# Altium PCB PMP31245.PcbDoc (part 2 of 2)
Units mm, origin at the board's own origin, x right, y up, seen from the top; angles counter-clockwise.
Board outline 106.43 x 50.29 mm, 4 copper layers (Top Layer, GND, Layer 2, Bottom Layer), stack 0.603 mm thick; 132 components, 64 nets, 341 pads, 146 vias.
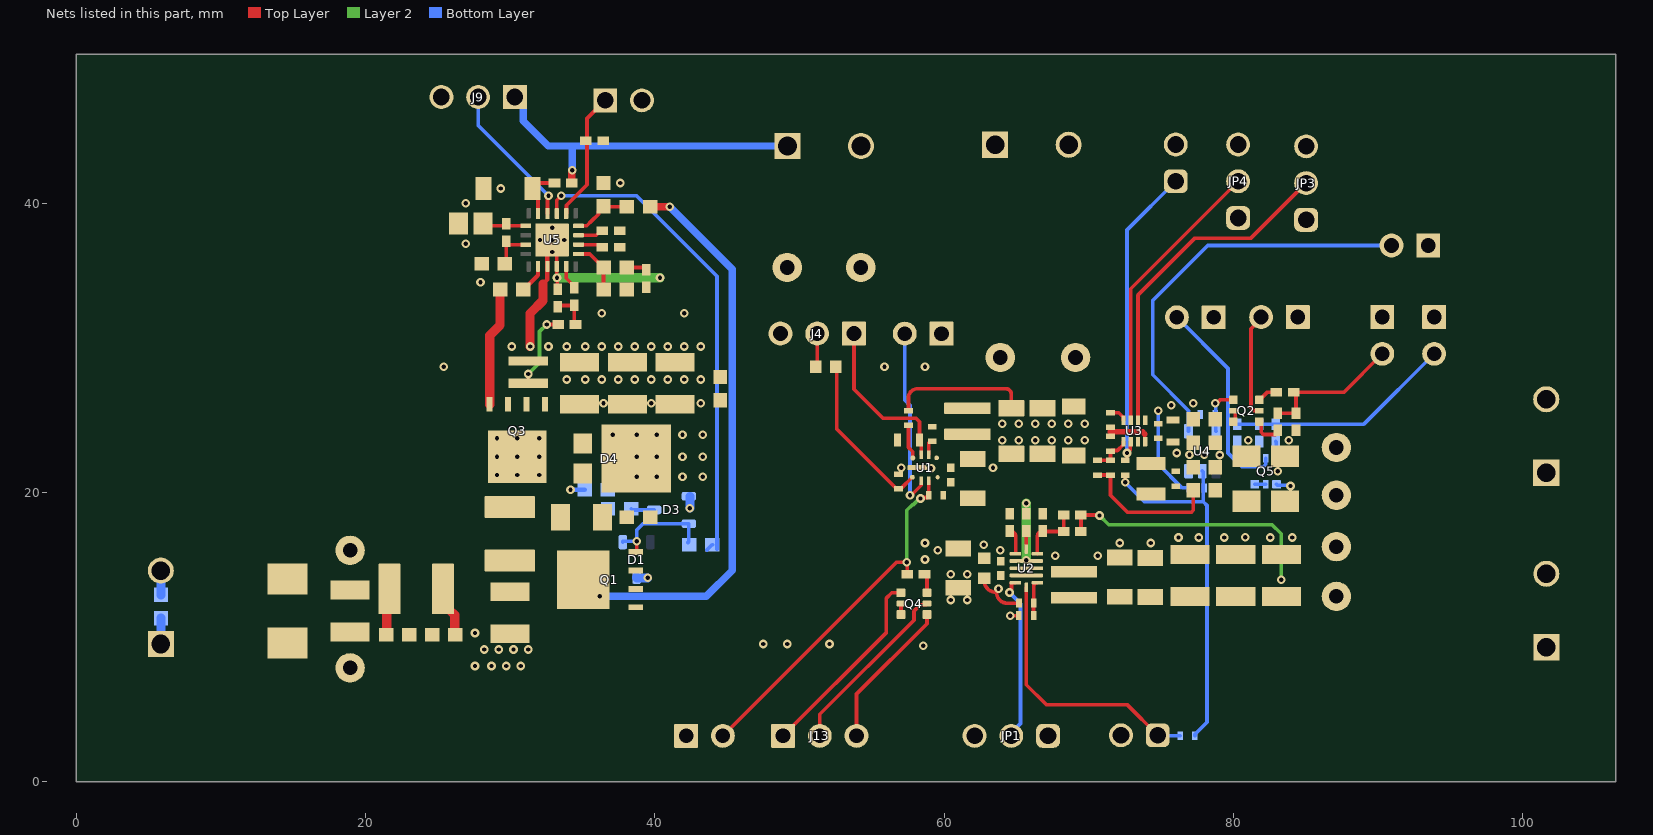
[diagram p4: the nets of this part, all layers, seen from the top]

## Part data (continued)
U4: library part CMP-0051406-2, "Single Buffer/Driver With Open-Drain Output, DBV0005A (SOT-23-5)", F @ Nom Voltage(Max)(Mhz)=250, Generic Part Number=SN74AUC1G07, ICC @ Nom Voltage(Max)(mA)=0.01, Manufacturer="Texas Instruments", Operating Temperature Range="-40 to 85 C", Rating=Catalog, tpd @ Nom Voltage(Max)(ns)=4.7,3.3,2.4,2.3,1.8, Voltage(Nom)(V)=0.8,1.2,1.5,1.8,2.5
U5: library part LM5150RUMQ1, "Wide VIN Automotive Low IQ Boost Controller, RUM0016C (WQFN-16)", Alternate Manufacturer="Texas Instruments"

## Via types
v1: diameter 0.6, hole 0.3, Top Layer to Bottom Layer, tented both sides, 143 vias
v2: diameter 0.6/0.6/0.6/0.6 (per signal layer), hole 0.3, Top Layer to Bottom Layer, tented both sides, 2 vias
v3: diameter 0.58, hole 0.3, Top Layer to Bottom Layer, tented both sides, 1 vias

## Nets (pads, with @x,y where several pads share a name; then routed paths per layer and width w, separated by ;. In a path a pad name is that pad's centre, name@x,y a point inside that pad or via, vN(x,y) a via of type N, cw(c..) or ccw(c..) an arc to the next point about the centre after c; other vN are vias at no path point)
3V3: C20.1 C21.1 C22.1 C23.1 C24.1 C25.1 J6.1 L3.2 Q5.4 R10.2 TP6.1 | length 10.9
  Top Layer w0.254: R10.2@70.612,21.209 C20.1@71.501,21.209 71.501,19.812 72.688,18.625 77.067,18.625 77.216,18.774 C23.1@77.216,20.155
  Bottom Layer w0.254: Q5.4@82.986,20.564 83.044,20.505 83.889,20.505 v1(83.947,20.447)
5V: C4.2 C5.2 C6.2 C9.1 C11.1 C12.1 C26.1 C27.1 C28.1 C29.2 C33.1 J1.1 JP1.1 JP3.1 JP4.1 L1.2 Q2.4 R2.1 R5.1 R33.2 TP1.1 U2.2@65.684,14.265 U3.1 U4.5 | length 23
  Top Layer w0.254: R2.1@57.531,25.654 57.531,26.543 cw(c58.166,26.543) 58.166,27.178 64.262,27.178 cw(c64.262,26.797) 64.643,26.797 C4.2@64.643,25.832 ; C11.1@62.763,14.065 62.763,13.945 ccw(c63.627,13.945) 63.627,13.081 ccw(c64.356,13.081) 64.356,12.352 R5.1@65.176,12.352 ; v1(78.74,26.162) 78.834,26.162 79.076,26.404 Q2.4@79.999,26.404 Q2.4@80.126,26.404
  Bottom Layer w0.254: v1(74.803,25.654) 74.803,21.971 76.454,20.32 R33.2@76.962,20.32 ; v1(78.74,26.162) 78.771,26.131 78.771,24.265 U4.5@78.801,24.235
  other v1: 60.452,12.573 61.595,12.573 63.754,13.335 60.452,14.351 61.595,14.351 64.008,24.765 65.151,24.765 66.294,24.765 67.437,24.765 68.58,24.765 69.723,24.765 75.692,26.035 77.216,26.162
12V: C1.2 C2.1 C31.1 C38.1 C39.1 C40.1 C41.1 D1.3 D4.3 J8.1 J9.1 Q1.1 Q1.2 Q1.3 R1.2 R21.2 TP10.1 U1.4 | length 24.3
  Top Layer w0.508: R21.2@34.255,41.402 34.255,42.256 v1(34.29,42.291)
  Bottom Layer w0.508: J9.1@30.319,47.347 30.89,46.776 30.89,45.691 32.62,43.961 34.29,43.961 ; v1(34.29,42.291) 34.29,43.961 ; J8.1@49.165,43.961 34.29,43.961
  Bottom Layer w0.635: D1.3@38.735,14.167 ccw(c38.805,14.167) 38.805,14.097 v1(39.497,14.097)
  other v1: 38.735,21.082 40.132,21.082 41.91,21.082 43.307,21.082 37.084,22.479 38.735,22.479 40.132,22.479 41.91,22.479 43.307,22.479 37.084,24.003 38.735,24.003 40.132,24.003 41.91,24.003 43.307,24.003 36.449,26.162 39.751,26.162 43.18,26.162
EN_LMR: J2.2 R1.1 R30.2 U1.3 | length 25.1
  Top Layer w0.254: J2.2@44.7,3.175 56.71,15.185 v1(57.419,15.185) ; R30.2@57.439,14.351 v1@57.439,15.185 ; v1(58.362,19.589) 58.428,19.655 58.864,19.655 58.926,19.716 58.926,20.815 U1.3@58.924,20.817
  Layer 2 w0.254: v1(57.419,15.185) 57.419,18.768 57.796,19.145 57.843,19.145 58.286,19.589 v1(58.362,19.589)
GND: C1.1 C2.2 C4.1 C5.1 C6.1 C7.2 C8.2 C9.2 C10.2 C11.2 C12.2 C14.2 C15.2 C16.2 C17.2 C18.2 C19.2 C21.2 C22.2 C23.2 C24.2 C25.2 C26.2 C27.2 C28.2 C29.1 C30.1 C33.2 C34.2 C35.1 C36.1 C37.2 C38.2 C39.2 C40.2 C41.2 C42.1 C43.1 C44.2 C45.2 C46.1 C48.2 D2.1 D3.1 J1.2 J2.1 J3.1 J4.3 J5.2 J6.2 J7.1 J8.2 J9.3 J10.2 J11.1 J12.1 J14.1 J15.1 J16.1 JP1.3 JP2.2 JP3.3 JP4.3 JP5.2 Q2.1 Q5.1 R3.2 R7.2 R8.1 R9.1 R11.1 R12.1 R19.1 R22.1 R23.1 R24.1 R26.1 R28.1 R32.1 TP2.1 TP5.1 TP7.1 TP9.1 TP11.1 U1.9 U2.4@65.684,15.265 U3.8 U4.3 U5.10 U5.11 U5.17@32.893,37.465 | length 31.6
  Top Layer w0.254: v1(32.893,37.465) 33.218,37.14 U5.11@33.218,35.64 33.221,35.637 33.221,34.851 v1(33.225,34.847) 33.251,34.821 33.251,34.151 C43.1@33.274,34.128 ; v1(64.57,11.487) R7.2@65.165,11.487 ; R11.1@71.501,23.876 71.501,24.194 R12.1@71.501,24.511 ; 73.879,24.038 73.879,23.54 U3.8@73.902,23.517 ; Q2.1@81.926,24.904 81.926,24.163 82.075,24.014 82.907,24.014 82.912,24.019 83.012,24.019 83.185,24.192 R28.1@83.185,24.292
  Top Layer w0.305: 32.258,34.417 32.568,34.727 U5.10@32.568,35.64 32.568,37.14 v1(32.893,37.465)
  Top Layer w0.381: 71.501,24.194 73.724,24.194 73.879,24.038
  Top Layer w0.635: v1(31.369,30.099) 31.369,32.385 32.258,33.274 32.258,34.417
  Layer 2 w0.635: v1(33.225,34.847) v2(40.354,34.846) v2(40.354,34.846) ; v3(65.679,15.316) v2(65.679,19.253)
  Bottom Layer w0.635: J7.1@5.834,9.517 5.843,9.526 5.843,11.312 C30.1@5.851,11.32 ; v1(42.418,18.923) D3.1@42.418,19.729
  other v1: 27.559,8.001 28.702,8.001 29.718,8.001 30.734,8.001 28.194,9.144 29.21,9.144 30.226,9.144 31.242,9.144 58.547,9.398 47.498,9.525 49.149,9.525 52.07,9.525 27.559,10.287 58.674,15.367 67.691,15.621 70.612,15.621 59.563,16.002 63.881,16.002 62.738,16.383 58.674,16.51 72.136,16.51 74.295,16.51 76.2,16.891 77.597,16.891 79.375,16.891 82.55,16.891 84.074,16.891 80.814,16.904 83.058,21.463 59.089,21.679 57.023,21.717 63.373,21.717 79.067,22.592 76.962,22.606 77.978,22.606 76.073,22.733 64.008,23.622 65.151,23.622 66.294,23.622 67.437,23.622 68.58,23.622 69.723,23.622 81.026,23.622 83.82,23.622 33.909,27.813 35.179,27.813 36.322,27.813 37.465,27.813 38.608,27.813 39.751,27.813 40.894,27.813 42.037,27.813 43.18,27.813 25.4,28.702 55.88,28.702 58.674,28.702 30.099,30.099 32.639,30.099 33.909,30.099 35.179,30.099 36.322,30.099 37.465,30.099 38.608,30.099 39.751,30.099 40.894,30.099 42.037,30.099 43.18,30.099 36.322,32.385 42.037,32.385 27.94,34.544 32.893,36.627 26.924,37.211 32.055,37.465 33.731,37.465 32.893,38.303 26.924,40.005 29.337,41.021 37.592,41.402
MODE: JP4.2 U3.3 | length 19.6
  Top Layer w0.254: U3.3@72.902,24.997 72.902,34.096 JP4.2@80.328,41.522
MODE/SYNC: R3.1 R4.2 U1.1 | length 11.7
  Top Layer w0.254: R4.2@52.578,28.829 52.578,24.392 56.723,20.247 R3.1@56.838,20.247 56.901,20.31 57.052,20.31 U1.1@57.797,21.056
NetC3_1: C3.1 U1.6 | length 1.1
  Top Layer w0.254: U1.6@58.924,22.617 58.924,23.403 59.064,23.543 C3.1@59.178,23.543
NetC3_2: C3.2 L1.1 U1.5
NetC7_1: C7.1 J12.2 R27.2 R28.2 | length 10
  Top Layer w0.254: R28.2@83.058,25.492 C7.1@84.328,25.492 84.328,26.762 R27.2@84.166,26.924 87.63,26.924 J12.2@90.297,29.591
NetC8_1: C8.1 J4.1 U1.7 | length 11.6
  Top Layer w0.254: J4.1@53.761,30.992 53.761,27.138 55.753,25.146 58.039,25.146 58.293,24.892 C8.1@58.293,23.622 58.293,23.431 58.424,23.3 U1.7@58.424,22.617
NetC10_1: C10.1 J15.2 R31.2 R32.2 | length 15.6
  Bottom Layer w0.254: R32.2@80.264,24.73 R31.2@82.931,24.73 89.023,24.73 J15.2@93.884,29.591
NetC13_2: C13.2 R6.1 R8.2 U2.5 | length 4.4
  Top Layer w0.254: U2.5@66.444,15.765 66.444,16.958 cw(c66.827,16.958) R8.2@66.827,17.34 ccw(c66.862,17.34) 66.862,17.305 R6.1@68.259,17.305 C13.2@68.259,18.448
NetC19_1: C19.1 U2.6 | length 1.3
  Top Layer w0.254: U2.6@65.684,16.09 C19.1@65.684,17.34
NetC20_2: C20.2 R10.1 R11.2 U3.5 | length 2.8
  Top Layer w0.254: R10.1@70.612,22.225 C20.2@71.501,22.225 R11.2@71.501,22.86 71.55,22.909 71.978,22.909 72.378,23.309 72.402,23.332 U3.5@72.402,23.517
NetC30_2: C30.2 C34.1 C35.2 D2.2 J7.2 L4.1 TP8.1 | length 4.9
  Top Layer w0.635: C35.2@21.454,10.164 21.454,13.144 L4.1@21.645,13.335
  Bottom Layer w0.635: J7.2@5.834,14.597 5.843,14.588 5.843,12.929 C30.2@5.851,12.92
NetC31_2: C31.2 R14.2
NetC32_1: C32.1 R13.1 | length 0.1
  Bottom Layer w0.305: C32.1@36.741,20.193 C32.1@36.792,20.244
NetC32_2: C32.2 D4.1 D4.2 L5.2 Q3.5 R14.1 | length 1
  Bottom Layer w0.305: v1(34.163,20.193) C32.2@35.141,20.193
  other v1: 29.083,21.209 30.48,21.209 32.004,21.209 29.083,22.479 30.48,22.479 32.004,22.479 29.083,23.749 30.48,23.749 32.004,23.749
NetC36_2: C36.2 C37.1 L4.2 L5.1 Q1.5 R15.1 | length 41.6
  Top Layer w0.508: R15.1@39.662,39.751 v1(41.021,39.751)
  Top Layer w0.635: L4.2@25.345,13.335 25.345,12.335 25.778,11.902 25.786,11.902 26.158,11.531 C36.2@26.158,10.202
  Bottom Layer w0.508: v1(36.195,12.827) 43.561,12.827 45.339,14.605 45.339,35.433 v1(41.021,39.751)
NetC42_2: C42.2 R15.2 U5.16 | length 4
  Top Layer w0.254: U5.16@34.718,38.44 35.292,38.44 35.657,38.805 36.101,39.249 36.101,39.454 C42.2@36.449,39.802 36.5,39.751 R15.2@38.062,39.751
NetC43_2: C43.2 R18.1 R20.2 | length 2.5
  Top Layer w0.254: C43.2@33.274,32.928 34.39,32.928 R20.2@34.419,32.957 34.419,31.713 R18.1@34.509,31.623
NetC44_1: C44.1 R21.1 U5.4 | length 3.6
  Top Layer w0.254: U5.4@31.918,39.29 31.918,40.648 C44.1@31.545,41.021 31.926,41.402 R21.1@33.055,41.402
NetC45_1: C45.1 R25.1 U5.7 | length 3
  Top Layer w0.254: C45.1@29.629,35.814 29.718,35.903 R25.1@29.718,37.313 ; R25.1@29.718,37.373 R25.1@29.718,37.313 ; U5.7@31.068,37.14 29.891,37.14 R25.1@29.718,37.313
NetC47_1: C47.1 C48.1 U5.13 | length 3.6
  Top Layer w0.254: U5.13@34.718,36.49 35.494,36.49 36.424,35.56 C47.1@36.449,35.56 C48.1@36.449,34.036
NetC47_2: C47.2 R26.2 | length 1.4
  Top Layer w0.254: C47.2@38.049,35.56 39.246,35.56 R26.2@39.408,35.398
NetD1_1: D1.1 D3.2 Q1.4 R16.1 | length 7.7
  Top Layer w0.254: Q1.4@38.662,15.875 ccw(c38.662,15.948) 38.735,15.948 v1(38.735,16.637)
  Bottom Layer w0.254: D1.1@37.785,16.567 cw(c37.855,16.567) 37.855,16.637 v1(38.735,16.637) 38.735,17.399 39.182,17.846 D3.2@42.348,17.846 42.348,16.605 R16.1@42.291,16.548
NetD3_3: D3.3 R13.2 | length 1.6
  Bottom Layer w0.254: R13.2@38.357,18.869 38.43,18.796 D3.3@39.948,18.796
NetJ4_2: J4.2 R4.1 | length 2.2
  Top Layer w0.254: R4.1@51.178,28.829 51.221,28.872 J4.2@51.221,30.992
NetJ9_2: J9.2 U5.3 | length 10.1
  Top Layer w0.254: U5.3@32.568,39.29 32.568,40.442 v1(32.639,40.513)
  Bottom Layer w0.254: J9.2@27.779,47.347 27.779,45.373 v1(32.639,40.513)
NetJ10_1: J10.1 R22.2 U5.1 | length 8.9
  Top Layer w0.254: U5.1@33.868,39.29 33.891,39.313 33.891,39.86 35.306,41.275 35.306,45.859 J10.1@36.564,47.118
NetJ11_2: J11.2 Q2.2 | length 7.2
  Top Layer w0.254: Q2.2@81.799,25.654 81.429,25.654 81.22,25.863 81.22,31.331 81.915,32.027 J11.2@81.915,32.131
NetJ13_1: J13.1 Q4.1 | length 13.6
  Top Layer w0.254: J13.1@48.862,3.175 56.007,10.32 56.007,12.7 56.376,13.069 Q4.1@57.012,13.069
NetJ13_2: J13.2 Q4.5 | length 12.4
  Top Layer w0.254: J13.2@51.402,3.175 51.402,4.666 57.912,11.176 57.912,11.811 58.347,12.246 58.739,12.246 Q4.5@58.812,12.319
NetJ13_3: J13.3 Q4.4 | length 10.4
  Top Layer w0.254: J13.3@53.942,3.175 53.942,6.063 58.812,10.933 Q4.4@58.812,11.569
NetJ14_2: J14.2 Q5.2 | length 14.3
  Bottom Layer w0.254: J14.2@76.093,32.118 79.629,28.582 79.629,22.733 80.578,21.784 82.087,21.784 82.236,21.933 Q5.2@82.236,22.364
NetJ16_2: J16.2 U4.4 | length 28.2
  Bottom Layer w0.254: U4.4@76.901,24.235 76.901,25.658 74.422,28.137 74.422,33.274 78.232,37.084 J16.2@90.932,37.084
NetJP1_2: JP1.2 U2.8 | length 11.5
  Top Layer w0.254: v1(64.516,13.081) 64.516,13.175 64.662,13.321 64.662,13.763 64.664,13.765 U2.8@64.923,13.765
  Bottom Layer w0.254: v1(64.516,13.081) 65.278,12.319 65.278,4.022 64.643,3.387 JP1.2@64.643,3.175
NetJP3_2: JP3.2 U3.2 | length 23.5
  Top Layer w0.254: U3.2@73.402,24.997 73.402,33.651 77.343,37.592 81.224,37.592 JP3.2@85.027,41.395
NetL2_1: L2.1 U2.3@65.684,14.765
NetL3_1: L3.1 U3.7
NetQ2_3: Q2.3 R27.1 | length 1.4
  Top Layer w0.254: Q2.3@81.799,26.404 82.319,26.924 R27.1@82.966,26.924
NetQ2_5: Q2.5 Q2.6 | length 0.8
  Top Layer w0.254: Q2.6@80.126,24.904 Q2.5@80.126,25.654
NetQ3_1: Q3.1 Q3.2 Q3.3 R18.2 R19.2 | length 5.4
  Top Layer w0.254: R19.2@31.242,27.546 v1(31.242,28.194) ; v1(32.512,31.623) R18.2@33.309,31.623
  Layer 2 w0.254: v1(31.242,28.194) 32.022,28.974 32.022,31.133 v1(32.512,31.623)
NetQ3_4: Q3.4 R17.2 | length 8.2
  Top Layer w0.635: Q3.4@28.575,26.089 28.575,30.861 29.299,31.585 R17.2@29.299,34.036
NetQ4_2: Q4.2 Q4.3 | length 0.8
  Top Layer w0.254: Q4.3@57.012,11.569 Q4.2@57.012,12.319
NetQ4_6: Q4.6 R30.1 | length 1.4
  Top Layer w0.254: R30.1@58.639,14.351 58.812,14.178 Q4.6@58.812,13.069
NetQ5_3: Q5.3 R31.1 | length 1.2
  Bottom Layer w0.254: R31.1@82.931,23.53 82.959,23.502 82.959,22.391 Q5.3@82.986,22.364
NetQ5_5: Q5.5 Q5.6 | length 0.8
  Bottom Layer w0.254: Q5.6@81.486,20.564 Q5.5@82.236,20.564
NetR2_2: R2.2 U1.8 | length 2.4
  Top Layer w0.254: R2.2@57.531,24.638 57.531,23.121 57.833,22.819 U1.8@57.833,22.382
NetR5_2: R5.2 R7.1 U2.1 | length 2.4
  Top Layer w0.254: R7.1@66.181,11.487 66.181,12.352 R5.2@66.192,12.352 66.192,13.512 cw(c66.444,13.512) U2.1@66.444,13.765
NetR9_2: R9.2 U2.7 | length 1.6
  Top Layer w0.254: R9.2@64.541,17.34 cw(c64.541,16.923) 64.958,16.923 64.958,15.93
NetR12_2: R12.2 U3.4 | length 1.2
  Top Layer w0.254: R12.2@71.501,25.527 71.508,25.52 72.064,25.52 72.379,25.205 72.402,25.182 U3.4@72.402,24.997
NetR16_2: R16.2 U5.2 | length 33.8
  Top Layer w0.254: U5.2@33.218,39.29 33.218,40.203 v1(33.528,40.513)
  Bottom Layer w0.254: v1(33.528,40.513) 38.735,40.513 44.291,34.957 R16.2@44.291,16.097 ; R16.2@43.607,16.01 43.607,16.035 43.955,16.383 R16.2@43.98,16.383
NetR17_1: R17.1 U5.9 | length 2
  Top Layer w0.305: R17.1@30.899,34.036 30.924,34.036 31.916,35.028 31.916,35.638 U5.9@31.918,35.64
NetR20_1: R20.1 U5.12 | length 1.7
  Top Layer w0.254: U5.12@33.868,35.64 33.868,34.808 34.419,34.257 R20.1@34.419,34.157
NetR23_2: R23.2 U5.14 | length 1.7
  Top Layer w0.254: U5.14@34.718,37.14 36.174,37.14 cw(c36.174,36.957) R23.2@36.357,36.957
NetR24_2: R24.2 U5.15 | length 1.8
  Top Layer w0.254: U5.15@34.718,37.79 35.947,37.79 36.257,38.1 R24.2@36.357,38.1
PG_3V3: JP5.1 R34.1 U3.6 | length 21.7
  Top Layer w0.254: R34.1@72.517,22.225 72.581,22.225 72.644,22.288 v1(72.644,22.733) 72.879,22.968 72.879,23.494 U3.6@72.902,23.517
  Bottom Layer w0.254: v1(72.644,22.733) 72.644,38.151 JP5.1@76.015,41.522
PG_5V: J3.2 U1.2 | length 12.5
  Top Layer w0.254: v1(57.644,19.812) 57.732,19.812 58.424,20.504 U1.2@58.424,20.644
  Bottom Layer w0.254: J3.2@57.277,30.988 57.277,26.389 57.644,26.022 v1(57.644,19.812)
PG_BUF: R29.2 R33.1 R34.2 U4.2 | length 25.2
  Top Layer w0.254: v1(72.517,20.701) R34.2@72.517,21.209
  Bottom Layer w0.254: v1(72.517,20.701) 73.85,19.367 77.915,19.367 ; R29.2@77.343,3.175 77.343,3.289 78.176,4.123 78.176,19.106 77.915,19.367 ; U4.2@77.851,21.485 77.915,21.421 77.915,19.367
PG_V97: JP2.1 R29.1 U2.9 | length 18.8
  Top Layer w0.254: U2.9@65.684,13.44 65.684,6.706 67.056,5.334 72.646,5.334 JP2.1@74.766,3.214
  Bottom Layer w0.254: JP2.1@74.766,3.214 74.805,3.175 R29.1@76.327,3.175
PVCC: C46.2 R25.2 U5.5 | length 3
  Top Layer w0.254: C46.2@28.116,38.608 28.284,38.44 U5.5@31.068,38.44
V97: C13.1 C14.1 C15.1 C16.1 C17.1 C18.1 J5.1 L2.2 R6.2 TP4.1 | length 18.7
  Top Layer w0.254: R6.2@69.459,17.305 C13.1@69.459,18.448 70.706,18.448 v1(70.739,18.415)
  Layer 2 w0.254: v1(70.739,18.415) 71.374,17.78 82.677,17.78 83.312,17.145 v1(83.312,13.97)
pads on no net: D1.2 U2.2@65.059,14.265 U2.2@66.309,14.265 U2.3@65.059,14.765 U2.3@66.309,14.765 U2.4@65.059,15.265 U2.4@66.309,15.265 U4.1 U5.6 U5.8 U5.17@32.283,36.855 U5.17@32.283,38.075 U5.17@33.503,36.855 U5.17@33.503,38.075 U5.A1 U5.A2 U5.A3 U5.A4

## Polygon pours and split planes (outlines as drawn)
5V on Top Layer "NONET_L01_P-001" (solid, pour order 91): 65.151,26.543 65.151,26.797 ccw(c64.008,26.797) 64.008,27.94 63.5,27.94 cw(c63.5,28.829) 62.611,28.829 62.611,30.099 cw(c63.246,30.099) 63.246,30.734 66.802,30.734 cw(c66.802,29.972) 67.564,29.972 67.564,26.543
GND on Top Layer "NONET_L01_P-001" (solid, pour order 90): 87.249,22.098 85.716,22.098 ccw(c85.716,21.321) 84.939,21.321 84.939,21.336 84.582,21.336 84.582,24.257 84.755,24.257 cw(c84.784,24.175) 84.866,24.205 ccw(c84.924,24.188) 84.94,24.13 87.249,24.13
12V on Top Layer "NONET_L01_P-001" (solid, pour order 88): 44.831,26.924 45.72,27.813 45.72,44.958 46.228,45.466 50.165,45.466 50.546,45.085 50.546,25.4 50.419,25.273 44.831,25.273
NetC32_2 on Top Layer "NONET_L01_P-001" (solid, pour order 85): 35.56,24.511 cw(c35.56,24.13) 35.941,24.13 35.941,20.066 cw(c35.56,20.066) 35.56,19.685 ccw(c35.56,19.431) 35.306,19.431 35.306,17.653 cw(c34.925,17.653) 34.925,17.272 24.257,17.272 cw(c24.257,17.907) 23.622,17.907 23.622,23.876 cw(c24.257,23.876) 24.257,24.511
12V on Top Layer "NONET_L01_P-001" (solid, pour order 83): 59.69,19.685 59.69,19.812 57.15,19.812 49.911,27.051 41.656,27.051 41.656,11.303 52.197,11.303 58.166,17.272 60.452,17.272
V97 on Top Layer "NONET_L01_P-001" (solid, pour order 81): 80.645,14.351 99.314,14.351 102.87,10.795 102.87,8.001 102.616,7.747 86.106,7.747 80.645,13.208
3V3 on Top Layer "NONET_L01_P-001" (solid, pour order 80): 83.947,20.701 84.836,20.701 85.344,21.209 89.662,21.209 91.059,22.606 103.251,22.606 103.505,22.352 103.505,19.558 102.235,18.288 83.947,18.288
NetL2_1 on Top Layer "NONET_L01_P-001" (solid, pour order 2): 66.802,14.605 cw(c66.802,14.351) 67.056,14.351 ccw(c67.31,14.351) 67.31,14.097 70.612,14.097 ccw(c70.612,14.224) 70.739,14.224 70.739,14.859 ccw(c70.649,14.87) 70.66,14.96 64.604,14.96 ccw(c64.61,14.866) 64.516,14.859 64.516,14.732 ccw(c64.643,14.732) 64.643,14.605
12V on Top Layer "NONET_L01_P-001" (solid, pour order 58): 43.18,27.051 cw(c43.18,26.67) 43.561,26.67 43.561,11.684 cw(c43.18,11.684) 43.18,11.303 38.1,11.303 cw(c38.1,11.557) 37.846,11.557 37.846,14.986 cw(c38.1,14.986) 38.1,15.24 39.243,15.24 ccw(c39.243,15.494) 39.497,15.494 39.497,16.383 ccw(c39.243,16.383) 39.243,16.637 cw(c39.243,16.764) 39.116,16.764 39.116,18.415 ccw(c37.846,18.415) 37.846,19.685 36.703,19.685 cw(c36.703,20.066) 36.322,20.066 36.322,24.13 ccw(c35.306,24.13) 35.306,25.146 33.401,25.146 cw(c33.401,25.4) 33.147,25.4 33.147,26.797 cw(c33.401,26.797) 33.401,27.051
GND on Top Layer "NONET_L01_P-001" (solid, pour order 72): 43.561,31.877 43.561,47.611 ccw(c42.491,47.611) 42.491,48.681 24.043,48.681 ccw(c24.043,47.625) 22.987,47.625 22.987,25.4 ccw(c23.622,25.4) 23.622,24.765 27.305,24.765 ccw(c27.305,25.4) 27.94,25.4 27.94,30.861 cw(c28.448,30.861) 28.448,31.369 43.053,31.369 ccw(c43.053,31.877)
GND on Top Layer "gnd" (solid, pour order 55): 32.258,28.575 cw(c32.258,27.813) 33.02,27.813 ccw(c33.401,27.813) 33.401,27.432 44.958,27.432 ccw(c44.894,27.876) 45.339,27.94 45.339,30.226 ccw(c44.831,30.226) 44.831,30.734 29.464,30.734 ccw(c29.464,30.48) 29.21,30.48 29.21,28.829 ccw(c29.464,28.829) 29.464,28.575
NetQ3_1 on Top Layer "NONET_L01_P-001" (solid, pour order 50): 29.718,25.4 cw(c29.718,25.654) 29.464,25.654 29.464,27.559 cw(c29.845,27.559) 29.845,27.94 32.639,27.94 cw(c32.639,27.813) 32.766,27.813 32.766,25.654 cw(c32.512,25.654) 32.512,25.4
NetC30_2 on Top Layer "NONET_L01_P-001" (solid, pour order 63): 5.08,11.557 cw(c5.08,12.319) 4.318,12.319 4.318,14.986 cw(c5.334,14.986) 5.334,16.002 21.717,16.002 cw(c21.717,15.24) 22.479,15.24 22.479,11.684 cw(c22.352,11.684) 22.352,11.557
GND on Top Layer "NONET_L01_P-001" (solid, pour order 64): 5.08,11.049 ccw(c5.08,10.414) 4.445,10.414 4.445,7.747 ccw(c5.08,7.747) 5.08,7.112 31.242,7.112 ccw(c31.242,7.493) 31.623,7.493 31.623,10.668 ccw(c31.369,10.668) 31.369,10.922 27.178,10.922 ccw(c27.178,10.541) 26.797,10.541 26.797,9.652 cw(c26.543,9.652) 26.543,9.398 25.654,9.398 cw(c25.654,9.652) 25.4,9.652 25.4,10.414 ccw(c25.019,10.414) 25.019,10.795 22.479,10.795 ccw(c22.479,10.541) 22.225,10.541 22.225,9.779 cw(c21.971,9.779) 21.971,9.525 20.828,9.525 cw(c20.828,9.652) 20.701,9.652 20.701,10.668 ccw(c20.32,10.668) 20.32,11.049
GND on Top Layer "NONET_L01_P-001" (solid, pour order 62): 37.592,33.528 40.513,33.528 ccw(c40.513,34.163) 41.148,34.163 41.148,38.227 ccw(c40.513,38.227) 40.513,38.862 37.465,38.862 ccw(c37.465,38.481) 37.084,38.481 37.084,36.703 ccw(c37.338,36.703) 37.338,36.449 cw(c37.338,36.322) 37.465,36.322 37.465,33.655 ccw(c37.592,33.655)
NetC36_2 on Top Layer "NONET_L01_P-001" (solid, pour order 61): 25.019,11.176 cw(c25.019,11.684) 24.511,11.684 24.511,14.986 cw(c26.289,14.986) 26.289,16.764 36.195,16.764 cw(c36.195,16.002) 36.957,16.002 36.957,11.557 cw(c36.576,11.557) 36.576,11.176
NetC31_2 on Top Layer "NONET_L01_P-001" (solid, pour order 53): 37.973,17.272 ccw(c37.973,17.907) 38.608,17.907 38.608,18.542 ccw(c37.846,18.542) 37.846,19.304 35.814,19.304 ccw(c35.814,19.177) 35.687,19.177 35.687,17.399 ccw(c35.814,17.399) 35.814,17.272
5V on Top Layer "NONET_L01_P-001" (solid, pour order 4): 66.294,14.478 64.506,14.469 cw(c64.515,14.612) 64.371,14.62 ccw(c64.26,14.62) 64.259,14.732 58.801,14.732 ccw(c58.801,14.351) 58.42,14.351 58.42,12.573 ccw(c58.801,12.573) 58.801,12.192 62.992,12.192 ccw(c62.992,13.335) 64.135,13.335 64.135,13.462 cw(c64.77,13.462) 64.77,14.097 66.78,14.097 ccw(c66.78,14.168) 66.851,14.168 66.851,14.395 ccw(c66.765,14.395) 66.765,14.48
12V on Top Layer "NONET_L01_P-001" (solid, pour order 17): 59.446,21.213 62.607,21.213 cw(c62.607,20.955) 62.865,20.955 62.865,17.78 cw(c62.357,17.78) 62.357,17.272 59.817,17.272 cw(c59.817,17.78) 59.309,17.78 59.309,21.167
GND on Top Layer "NONET_L01_P-001" (solid, pour order 16): 57.023,23.368 57.023,22.529 ccw(c57.548,22.529) 57.548,22.004 60.104,22.004 ccw(c60.104,22.606) 60.706,22.606 cw(c61.214,22.606) 61.214,23.114 63.373,23.114 ccw(c63.373,23.368) 63.627,23.368 cw(c64.262,23.368) 64.262,24.003 69.596,24.003 cw(c69.596,23.622) 69.977,23.622 69.977,21.717 cw(c69.596,21.717) 69.596,21.336 56.769,21.336 cw(c56.769,21.59) 56.515,21.59 56.515,23.241 cw(c56.642,23.241) 56.642,23.368
NetC3_2 on Top Layer "NONET_L01_P-001" (solid, pour order 15): 59.834,22.217 59.936,22.217 ccw(c59.936,22.479) 60.198,22.479 cw(c61.214,22.479) 61.214,23.495 63.136,23.495 ccw(c63.136,23.634) 63.274,23.634 63.274,24.356 ccw(c63.119,24.356) 63.119,24.511 59.817,24.511 cw(c59.817,24.638) 59.69,24.638 ccw(c59.563,24.638) 59.563,24.765 58.928,24.765 ccw(c58.928,24.638) 58.801,24.638 58.801,24.384 ccw(c58.928,24.384) 58.928,24.257 59.055,24.257 cw(c59.055,23.622) 59.69,23.622 59.69,23.368 cw(c59.436,23.368) 59.436,23.114 ccw(c59.436,22.978) 59.3,22.978 59.3,22.267 ccw(c59.349,22.267) 59.349,22.217
5V on Top Layer "NONET_L01_P-001" (solid, pour order 13): 63.373,25.273 cw(c63.373,25.019) 63.627,25.019 ccw(c64.262,25.019) 64.262,24.384 69.85,24.384 ccw(c69.85,24.638) 70.104,24.638 70.104,26.416 ccw(c69.85,26.416) 69.85,26.67 59.944,26.67 ccw(c59.944,26.416) 59.69,26.416 59.69,25.527 ccw(c59.944,25.527) 59.944,25.273
GND on Top Layer "NONET_L01_P-001" (solid, pour order 12): 67.056,19.558 cw(c67.056,19.431) 67.183,19.431 67.183,18.161 cw(c67.056,18.161) 67.056,18.034 64.262,18.034 cw(c64.262,18.161) 64.135,18.161 64.135,19.431 cw(c64.262,19.431) 64.262,19.558
3V3 on Top Layer "NONET_L01_P-001" (solid, pour order 10): 73.279,19.177 ccw(c73.533,19.177) 73.533,18.923 77.978,18.923 cw(c77.978,18.542) 78.359,18.542 ccw(c78.613,18.542) 78.613,18.288 84.709,18.288 ccw(c84.709,18.542) 84.963,18.542 84.963,20.447 ccw(c84.709,20.447) 84.709,20.701 73.533,20.701 ccw(c73.533,20.447) 73.279,20.447
GND on Top Layer "NONET_L01_P-001" (solid, pour order 8): 73.759,23.546 73.759,23.142 ccw(c73.914,23.142) 73.914,22.987 75.311,22.987 cw(c75.311,22.606) 75.692,22.606 75.692,21.209 ccw(c75.819,21.209) 75.819,21.082 84.7,21.082 ccw(c84.7,21.321) 84.939,21.321 84.939,24.027 ccw(c84.709,24.027) 84.709,24.257 73.886,24.257 ccw(c73.886,24.126) 73.755,24.126
5V on Top Layer "NONET_L01_P-001" (solid, pour order 7): 73.733,24.692 ccw(c73.914,24.692) 73.914,24.511 79.502,24.511 ccw(c79.502,24.765) 79.756,24.765 79.756,26.543 ccw(c79.375,26.543) 79.375,26.924 75.365,26.924 ccw(c75.365,25.293) 73.735,25.241
NetL3_1 on Top Layer "NONET_L01_P-001" (solid, pour order 6): 73.252,23.486 73.252,21.49 ccw(c73.279,21.49) 73.279,21.463 75.184,21.463 ccw(c75.184,21.59) 75.311,21.59 75.311,22.479 ccw(c75.184,22.479) 75.184,22.606 74.304,22.606 cw(c74.304,23.363) 73.548,23.363 73.548,23.371 ccw(c73.402,23.371) 73.402,23.517
GND on Top Layer "NONET_L01_P-001" (solid, pour order 5): 70.866,14.986 cw(c70.866,14.859) 70.993,14.859 ccw(c71.247,14.859) 71.247,14.605 88.011,14.732 ccw(c88.011,15.24) 88.519,15.24 88.519,17.272 ccw(c88.075,17.209) 88.011,17.653 70.866,17.653 ccw(c70.866,16.891) 70.104,16.891 cw(c69.723,16.891) 69.723,16.51 67.691,16.51 ccw(c67.691,15.875) 67.056,15.875 67.056,15.621 cw(c66.929,15.621) 66.929,15.494 64.504,15.494 cw(c64.504,15.685) 64.313,15.685 64.313,15.951 ccw(c63.373,15.951) 63.373,16.891 58.674,16.891 ccw(c58.674,16.51) 58.293,16.51 58.293,15.367 ccw(c58.674,15.367) 58.674,14.986
V97 on Top Layer "NONET_L01_P-001" (solid, pour order 3): 67.691,13.462 ccw(c67.691,13.081) 67.31,13.081 67.31,12.065 ccw(c67.691,12.065) 67.691,11.684 84.582,11.684 ccw(c84.582,12.065) 84.963,12.065 84.963,13.97 ccw(c84.582,13.97) 84.582,14.351 71.882,14.351 ccw(c71.882,13.843) 71.374,13.843 cw(c70.993,13.843) 70.993,13.462
GND on GND "NONET_L01_P-001" (solid, pour order 82): 105.537,49.022 105.537,1.397 43.561,1.397 43.561,49.022 44.958,49.022
GND on GND "NONET_L01_P-001" (solid, pour order 68): 43.942,30.734 23.749,30.734 22.987,29.972 22.987,25.273 23.368,24.892 35.814,24.892 36.195,24.511 36.195,17.653 35.306,16.764 25.527,16.764 24.638,15.875 24.638,2.032 25.273,1.397 43.942,1.397
GND on GND "NONET_L01_P-001" (solid, pour order 66): 43.18,31.115 43.18,48.26 42.672,48.768 23.241,48.768 22.987,48.514 22.987,29.21 23.495,28.702 32.258,28.702 34.668,30.712 34.671,31.115 36.576,31.115
GND on Bottom Layer "NONET_L01_P-001" (solid, pour order 89): 105.029,49.657 105.537,49.149 105.537,1.524 104.902,0.889 39.243,0.889 38.735,1.397 38.735,10.414 39.497,11.176 44.196,11.176 46.355,13.335 46.355,48.895 47.117,49.657
GND on Bottom Layer "NONET_L01_P-001" (solid, pour order 75): 43.688,31.115 43.688,31.242 43.688,47.625 ccw(c42.545,47.625) 42.545,48.768 23.749,48.768 ccw(c23.749,48.006) 22.987,48.006 22.987,25.527 ccw(c23.622,25.527) 23.622,24.892 32.258,24.892 ccw(c32.258,25.4) 32.766,25.4 32.766,26.924 cw(c33.274,26.924) 33.274,27.432 43.307,27.432 ccw(c43.307,27.813) 43.688,27.813 43.688,30.861
NetC32_2 on Bottom Layer "NONET_L01_P-001" (solid, pour order 86): 33.175,24.39 cw(c33.175,24.009) 33.556,24.009 33.556,19.431 cw(c33.176,19.431) 33.175,19.05 26.035,19.05 cw(c26.036,19.559) 25.527,19.558 25.527,24.009 cw(c25.905,24.009) 25.905,24.387
12V on Bottom Layer "NONET_L01_P-001" (solid, pour order 74): 33.147,25.4 ccw(c33.528,25.4) 33.528,25.019 35.56,25.019 cw(c35.56,24.511) 36.068,24.511 36.068,21.59 ccw(c36.576,21.59) 36.576,21.082 37.338,21.082 cw(c37.338,20.828) 37.592,20.828 37.592,20.193 ccw(c37.973,20.193) 37.973,19.812 41.275,19.812 ccw(c41.275,20.193) 41.656,20.193 cw(c41.783,20.193) 41.783,20.32 43.307,20.32 ccw(c43.307,20.701) 43.688,20.701 43.688,26.67 ccw(c43.434,26.67) 43.434,26.924 33.401,26.924 ccw(c33.401,26.67) 33.147,26.67
NetC32_1 on Bottom Layer "NONET_L01_P-001" (solid, pour order 59): 36.161,18.354 36.161,20.64 cw(c36.288,20.64) 36.288,20.767 37.177,20.767 cw(c37.177,20.64) 37.304,20.64 37.304,18.354 cw(c37.177,18.354) 37.177,18.227 36.288,18.227 cw(c36.288,18.354)
GND on Layer 2 "NONET_L01_P-001" (solid, pour order 69): 42.545,48.768 44.196,47.117 44.196,5.969 25.146,5.969 24.511,6.604 24.511,15.494 22.987,17.018 22.987,48.514 23.241,48.768
GND on Layer 2 "NONET_L01_P-001" (solid, pour order 87): 43.942,30.734 61.087,30.734 61.214,30.607 61.214,6.604 60.579,5.969 43.815,5.969 43.942,6.096
5V on Layer 2 "NONET_L01_P-001" (solid, pour order 84): 88.646,3.048 88.646,47.117 87.63,48.133 60.579,48.133 59.69,47.244 59.69,19.304 59.69,2.286 60.452,1.524 87.122,1.524

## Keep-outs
Keep-Out Layer:
  text ".Layer_Name" at 21.971,-14.719 h1.52
  text ".Layer_Name" at -11.465,-236.84 h1.52

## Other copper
Top Layer:
  text ".Layer_Name" at 21.971,-14.719 h1.52
  text ".Layer_Name" at -11.465,-236.84 h1.52
Layer 2:
  pour cut-out: 44.577,30.734 34.544,30.734 34.544,31.115 44.577,31.115
Bottom Layer:
  pour cut-out: 43.942,31.115 34.671,31.115 34.671,30.734 43.942,30.734
  text ".Layer_Name" at 21.971,-14.719 h1.52
  text ".Layer_Name" at -11.465,-236.84 h1.52

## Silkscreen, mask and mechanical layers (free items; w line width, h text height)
Top Overlay:
  lines w0.254: 13.586,34.402 13.183,34.65 13.494,34.09 12.926,34.613 13.476,33.788 12.66,34.595 13.531,33.458 12.319,34.671 13.589,33.274 ; 71.628,20.066 72.39,20.574 ; 6.096,27.305 6.096,34.671 13.589,34.671 13.589,27.305 6.096,27.305 ; 56.261,10.911 56.261,27.686 85.217,27.686 85.217,10.911 56.261,10.911
  text "*" at 93.472,46.355 h1.52
  text "PMP31245" at 0.762,41.583 h5
  text "Rev. E1" at 0.762,38.765 h3
  text "*" at 72.644,25.781 h1.52
  text ".Layer_Name" at 21.971,-14.719 h1.52
  text ".Layer_Name" at -11.465,-236.84 h1.52
Bottom Overlay:
  text ".Layer_Name" at 21.971,-14.719 h1.52
  text ".Layer_Name" at -11.465,-236.84 h1.52
Top Paste:
  text ".Layer_Name" at 21.971,-14.719 h1.52
  text ".Layer_Name" at -11.465,-236.84 h1.52
Bottom Paste:
  text ".Layer_Name" at 21.971,-14.719 h1.52
  text ".Layer_Name" at -11.465,-236.84 h1.52
Top Solder:
  text ".Layer_Name" at 21.971,-14.719 h1.52
  text ".Layer_Name" at 21.971,-14.719 h1.52
  text ".Layer_Name" at -11.465,-236.84 h1.52
  text ".Layer_Name" at -11.465,-236.84 h1.52
Bottom Solder:
  text ".Layer_Name" at 21.971,-14.719 h1.52
  text ".Layer_Name" at -11.465,-236.84 h1.52
Drill Guide:
  text ".Layer_Name" at 21.971,-14.719 h1.52
  text ".Layer_Name" at -11.465,-236.84 h1.52
Mechanical 1:
  lines w0.254: 0,0 0,50.292 54.102,50.292 106.426,50.292 106.426,0 0,0
  text ".Layer_Name" at 21.971,-14.719 h1.52
  text ".Layer_Name" at -11.465,-236.84 h1.52
Mechanical 2:
  text ".Layer_Name" at 21.971,-14.719 h1.52
  text ".Layer_Name" at -11.465,-236.84 h1.52
Mechanical 3:
  text ".Layer_Name" at 21.971,-14.719 h1.52
  text ".Layer_Name" at -11.465,-236.84 h1.52
Mechanical 6:
  text ".Layer_Name" at 21.971,-14.719 h1.52
  text ".Layer_Name" at -11.465,-236.84 h1.52
Mechanical 5:
  lines w0.254: -33.538,-238.66 134.102,-238.66 ; -33.538,-233.496 134.153,-233.496 ; -33.538,-228.331 -33.538,-243.825 68.189,-243.825 134.153,-243.825 134.153,-228.331 -33.525,-228.331 -33.525,-243.825 6.493,-243.825 ; -0.102,-16.54 167.538,-16.54 ; -0.102,-11.375 167.589,-11.375 ; -0.102,-6.21 -0.102,-21.704 101.625,-21.704 167.589,-21.704 167.589,-6.21 -0.089,-6.21 -0.089,-21.704 39.929,-21.704 ; 29.073,-243.825 29.073,-228.331 ; 61.255,-233.496 61.255,-228.331 ; 62.509,-21.704 62.509,-6.21 ; 82.591,-233.496 82.591,-228.331 ; 94.691,-11.375 94.691,-6.21 ; 98.39,-243.99 98.39,-238.838 ; 116.027,-11.375 116.027,-6.21 ; 131.826,-21.869 131.826,-16.717
  text "PCB VIEWED FROM TOP SIDE" at 1.511,-9.567 h1.52
  text "BOARD #:" at 64.414,-9.567 h1.52
  text ".PRJ_Number" at 78.27,-9.567 h1.52
  text "REV:" at 99.72,-9.567 h1.52
  text ".PCB_Rev" at 107.124,-9.567 h1.52
  text "SVN REV:" at 121.006,-9.567 h1.52
  text ".VersionControl_RevNumber" at 133.858,-9.567 h1.52
  text "TID #:" at 64.414,-14.732 h1.52
  text ".TID" at 78.27,-14.732 h1.52
  text "PLOT NAME =" at 1.511,-19.948 h1.52
  text ".plot_File_Name" at 21.971,-19.948 h1.52
  text "GENERATED    :" at 64.465,-19.948 h1.52
  text ".Print_Date" at 86.55,-19.948 h1.52
  text ".Print_Time" at 105.067,-19.948 h1.52
  text "TEXAS INSTRUMENTS" at 137.185,-19.948 h1.52
  text "PCB VIEWED FROM TOP SIDE" at -31.925,-231.688 h1.52
  text "BOARD #:" at 30.978,-231.688 h1.52
  text ".PRJ_Number" at 44.834,-231.688 h1.52
  text "REV:" at 66.284,-231.688 h1.52
  text ".PCB_Rev" at 73.688,-231.688 h1.52
  text "SVN REV:" at 87.569,-231.688 h1.52
  text ".VersionControl_RevNumber" at 100.422,-231.688 h1.52
  text "TID #:" at 30.978,-236.853 h1.52
  text ".TID" at 44.834,-236.853 h1.52
  text "PLOT NAME =" at -31.925,-242.068 h1.52
  text ".plot_File_Name" at -11.465,-242.068 h1.52
  text "GENERATED    :" at 31.029,-242.068 h1.52
  text ".Print_Date" at 53.114,-242.068 h1.52
  text ".Print_Time" at 71.631,-242.068 h1.52
  text "TEXAS INSTRUMENTS" at 103.749,-242.068 h1.52
Mechanical 6 (Mech6):
  lines w0.254: -33.551,-233.508 134.14,-233.508 ; -33.5,-238.673 134.14,-238.673 ; -0.114,-11.388 167.576,-11.388 ; -0.064,-16.552 167.576,-16.552 ; 2.213,-244.003 2.213,-238.851 ; 18.011,-233.508 18.011,-228.344 ; 35.649,-21.882 35.649,-16.73 ; 39.347,-233.508 39.347,-228.344 ; 51.448,-11.388 51.448,-6.223 ; 71.529,-243.838 71.529,-228.344 ; 72.784,-11.388 72.784,-6.223 ; 94.11,-243.838 134.128,-243.838 134.128,-228.344 -33.551,-228.344 -33.551,-243.838 32.413,-243.838 134.14,-243.838 134.14,-228.344 ; 104.965,-21.717 104.965,-6.223 ; 127.546,-21.717 167.564,-21.717 167.564,-6.223 -0.114,-6.223 -0.114,-21.717 65.849,-21.717 167.576,-21.717 167.576,-6.223
  text ".VersionControl_RevNumber" at 33.617,-9.58 h1.52
  text "SVN REV:" at 46.469,-9.58 h1.52
  text ".PCB_Rev" at 60.35,-9.58 h1.52
  text "REV:" at 67.754,-9.58 h1.52
  text ".PRJ_Number" at 89.205,-9.58 h1.52
  text "BOARD #:" at 103.06,-9.58 h1.52
  text "PCB VIEWED FROM BOTTOM SIDE" at 165.964,-9.58 h1.52
  text ".TID" at 89.205,-14.745 h1.52
  text "TID #:" at 103.06,-14.745 h1.52
  text "TEXAS INSTRUMENTS" at 30.29,-19.96 h1.52
  text ".Print_Time" at 62.408,-19.96 h1.52
  text ".Print_Date" at 80.924,-19.96 h1.52
  text "GENERATED    :" at 103.01,-19.96 h1.52
  text ".plot_File_Name" at 145.504,-19.96 h1.52
  text "PLOT NAME =" at 165.964,-19.96 h1.52
  text ".VersionControl_RevNumber" at 0.181,-231.701 h1.52
  text "SVN REV:" at 13.033,-231.701 h1.52
  text ".PCB_Rev" at 26.914,-231.701 h1.52
  text "REV:" at 34.318,-231.701 h1.52
  text ".PRJ_Number" at 55.769,-231.701 h1.52
  text "BOARD #:" at 69.624,-231.701 h1.52
  text "PCB VIEWED FROM BOTTOM SIDE" at 132.527,-231.701 h1.52
  text ".TID" at 55.769,-236.865 h1.52
  text "TID #:" at 69.624,-236.865 h1.52
  text "TEXAS INSTRUMENTS" at -3.147,-242.081 h1.52
  text ".Print_Time" at 28.972,-242.081 h1.52
  text ".Print_Date" at 47.488,-242.081 h1.52
  text "GENERATED    :" at 69.573,-242.081 h1.52
  text ".plot_File_Name" at 112.068,-242.081 h1.52
  text "PLOT NAME =" at 132.527,-242.081 h1.52
Mechanical 10:
  text ".Layer_Name" at 21.971,-14.719 h1.52
  text ".Layer_Name" at -11.465,-236.84 h1.52
Mechanical 11:
  lines w0.254: -33.538,-238.66 134.102,-238.66 ; -33.538,-233.496 134.153,-233.496 ; -33.538,-228.331 -33.538,-243.825 68.189,-243.825 134.153,-243.825 134.153,-228.331 -33.525,-228.331 -33.525,-243.825 6.493,-243.825 ; -0.102,-16.54 167.538,-16.54 ; -0.102,-11.375 167.589,-11.375 ; -0.102,-6.21 -0.102,-21.704 101.625,-21.704 167.589,-21.704 167.589,-6.21 -0.089,-6.21 -0.089,-21.704 39.929,-21.704 ; 29.073,-243.825 29.073,-228.331 ; 61.255,-233.496 61.255,-228.331 ; 62.509,-21.704 62.509,-6.21 ; 82.591,-233.496 82.591,-228.331 ; 94.691,-11.375 94.691,-6.21 ; 98.39,-243.99 98.39,-238.838 ; 116.027,-11.375 116.027,-6.21 ; 131.826,-21.869 131.826,-16.717
  text "ALL ARTWORK VIEWED FROM TOP SIDE" at 1.511,-9.567 h1.52
  text "BOARD #:" at 64.414,-9.567 h1.52
  text ".PRJ_Number" at 78.27,-9.567 h1.52
  text "REV:" at 99.72,-9.567 h1.52
  text ".PCB_Rev" at 107.124,-9.567 h1.52
  text "SVN REV:" at 121.006,-9.567 h1.52
  text ".VersionControl_RevNumber" at 133.858,-9.567 h1.52
  text "LAYER NAME =" at 1.511,-14.719 h1.52
  text "TID #:" at 64.414,-14.732 h1.52
  text ".TID" at 78.27,-14.732 h1.52
  text "PLOT NAME =" at 1.511,-19.948 h1.52
  text ".plot_File_Name" at 21.971,-19.948 h1.52
  text "GENERATED    :" at 64.465,-19.948 h1.52
  text ".Print_Date" at 86.55,-19.948 h1.52
  text ".Print_Time" at 105.067,-19.948 h1.52
  text "TEXAS INSTRUMENTS" at 137.185,-19.948 h1.52
  text "ALL ARTWORK VIEWED FROM TOP SIDE" at -31.925,-231.688 h1.52
  text "BOARD #:" at 30.978,-231.688 h1.52
  text ".PRJ_Number" at 44.834,-231.688 h1.52
  text "REV:" at 66.284,-231.688 h1.52
  text ".PCB_Rev" at 73.688,-231.688 h1.52
  text "SVN REV:" at 87.569,-231.688 h1.52
  text ".VersionControl_RevNumber" at 100.422,-231.688 h1.52
  text "LAYER NAME =" at -31.925,-236.84 h1.52
  text "TID #:" at 30.978,-236.853 h1.52
  text ".TID" at 44.834,-236.853 h1.52
  text "PLOT NAME =" at -31.925,-242.068 h1.52
  text ".plot_File_Name" at -11.465,-242.068 h1.52
  text "GENERATED    :" at 31.029,-242.068 h1.52
  text ".Print_Date" at 53.114,-242.068 h1.52
  text ".Print_Time" at 71.631,-242.068 h1.52
  text "TEXAS INSTRUMENTS" at 103.749,-242.068 h1.52
Mechanical 12:
  text ".Layer_Name" at 21.971,-14.719 h1.52
  text ".Layer_Name" at -11.465,-236.84 h1.52
Mechanical 13:
  text ".Layer_Name" at 21.971,-14.719 h1.52
  text ".Layer_Name" at -11.465,-236.84 h1.52
Mechanical 14:
  text ".Layer_Name" at 21.971,-14.719 h1.52
  text ".Layer_Name" at -11.465,-236.84 h1.52
Mechanical 15:
  text ".Layer_Name" at 21.971,-14.719 h1.52
  text ".Layer_Name" at -11.465,-236.84 h1.52
Mechanical 16:
  text ".Layer_Name" at 21.971,-14.719 h1.52
  text ".Layer_Name" at -11.465,-236.84 h1.52
Drill Drawing:
  text ".Layer_Name" at 21.971,-14.719 h1.52
  text ".Layer_Name" at -11.465,-236.84 h1.52

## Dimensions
56.261,10.911 to 56.261,27.686 on Top Overlay
56.261,10.911 to 85.217,10.911 on Top Overlay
